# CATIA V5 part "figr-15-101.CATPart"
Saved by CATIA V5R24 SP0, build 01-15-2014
Part number: Part1
Bounding box of the stored display mesh (mm): x -52.43 to 60.529, y -25.631 to 32.893, z 0 to 4
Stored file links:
  D:\KAVITA\CATIA V5-6R2014 Project_ Kavita\CATIA V5-6R2014_partfiles\Partfiles\c15_catia_v5-6r2014_prt\figr-15-101.CATPart
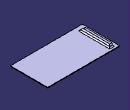
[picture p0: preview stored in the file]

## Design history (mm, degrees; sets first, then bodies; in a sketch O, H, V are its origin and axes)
SheetMetalParameters1: Thickness 1, BendRadius 5, KFactor 0.5 {= log(min(100,max(20*SheetMetalParameters1.BendRadius,SheetMetalParameters1.Thickness)/SheetMetalParameters1.Thickness))/log(100)/2}, ReliefRadialLength 1, ReliefAxialLength 2, MinimumBendRadius 0
Body1 (main body)
  Sketch1 on xy-plane, origin (0, 0, 0), H (1, 0, 0), V (0, 1, 0)
    line L1 (-52.4297, 32.8934) -> (60.5286, 32.8934)
    line L2 (60.5286, 32.8934) -> (60.5286, -25.6312)
    line L3 (60.5286, -25.6312) -> (-52.4297, -25.6312)
    line L4 (-52.4297, -25.6312) -> (-52.4297, 32.8934)
    horizontal: L1 H, L3 H
    vertical: L2 V, L4 V
  Wall1: Thickness 1, Profile Sketch1
  Sketch2 on face of Wall1, origin (0, 0, 1), H (1, 0, 0), V (0, 1, 0)
    line L1 (-47.3159, -16.5837) -> (-43.073, -16.5837)
    line L2 (-43.073, -16.5837) -> (-43.073, 26.788)
    line L3 (-43.073, 26.788) -> (-47.3159, 26.788)
    line L4 (-47.3159, 26.788) -> (-47.3159, -16.5837)
    horizontal: L1 H, L3 H
    vertical: L2 V, L4 V
  d_Stamp1: Stamp_FilletRadius 2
